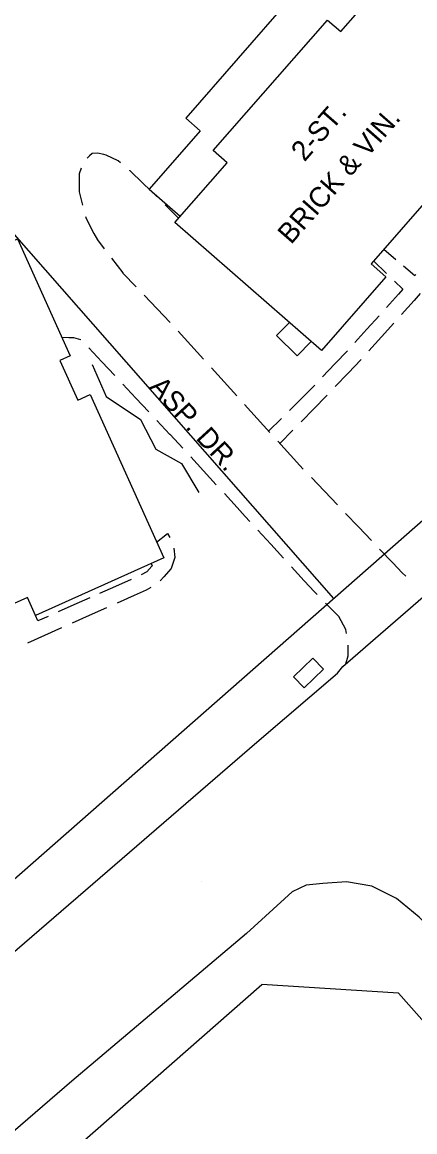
# Model space of a CAD drawing. Extents: x 2443269 to 2494951, y 591171 to 622130.
# Drawn here: x 2462410.9 to 2462491.9, y 604001.8 to 604230.6 of the extents above; entities that cross this region are included whole.
import ezdxf

# ---------------------------------------------------------------- set-up
doc = ezdxf.new("R2010")
doc.units = 0
for name, color, linetype in [('SURVEY - NON-TRANSPORTATION - Buildings', 7, 'Continuous'), ('SURVEY - NON-TRANSPORTATION - Buildings Text', 7, 'Continuous'), ('SURVEY - NON-TRANSPORTATION - Features', 7, 'Continuous'), ('SURVEY - PROPERTY - Property Lines', 7, 'Continuous'), ('SURVEY - PROPERTY - ROW Lines', 7, 'Continuous'), ('SURVEY - TRANSPORTATION - Features', 7, 'Continuous'), ('SURVEY - TRANSPORTATION - Features Text', 7, 'Continuous'), ('SURVEY - TRANSPORTATION - Roads', 7, 'Continuous')]:
    doc.layers.add(name, color=color, linetype=linetype)

msp = doc.modelspace()

# ---------------------------------------------------------------- linework, layer by layer
at = {"layer": 'SURVEY - NON-TRANSPORTATION - Buildings'}
for points in [[(2462442.414, 604189.35), (2462453.178, 604201.646), (2462450.334, 604204.137), (2462473.89, 604231.053), (2462476.61, 604228.671), (2462487.141, 604240.701), (2462517.338, 604214.271), (2462503.897, 604198.913), (2462500.954, 604201.489), (2462482.844, 604180.797), (2462485.914, 604178.11), (2462472.617, 604162.916)], [(2462330.229, 604111.45), (2462353.392, 604121.886), (2462351.827, 604125.36), (2462353.142, 604125.951), (2462351.062, 604130.567), (2462327.024, 604119.737), (2462316.345, 604143.444), (2462338.638, 604153.487), (2462336.935, 604157.27), (2462386.213, 604179.468), (2462387.788, 604175.974), (2462409.983, 604185.974), (2462420.855, 604161.84), (2462418.713, 604160.876), (2462422.397, 604152.7), (2462424.953, 604153.851), (2462440.111, 604120.206), (2462413.68, 604108.3), (2462412.004, 604112.024), (2462370.199, 604093.192), (2462371.879, 604089.465), (2462345.488, 604077.575)]]:
    msp.add_lwpolyline(points, close=True, dxfattribs=at)
at = {"layer": 'SURVEY - NON-TRANSPORTATION - Features'}
for points in [[(2462486.315, 604239.757), (2462480.052, 604245.219), (2462469.349, 604232.946), (2462466.262, 604235.639), (2462444.648, 604210.856), (2462447.647, 604208.241), (2462437.122, 604196.174), (2462443.51, 604190.603)], [(2462470.504, 604164.767), (2462467.597, 604161.82), (2462463.349, 604166.01), (2462466.006, 604168.704)], [(2462425.383, 604160.055), (2462428.231, 604153.458), (2462435.298, 604148.727), (2462438.516, 604142.578), (2462443.775, 604139.603), (2462447.361, 604133.631)]]:
    msp.add_lwpolyline(points, dxfattribs=at)
msp.add_lwpolyline([(2462469.048, 604093.385), (2462466.872, 604095.636), (2462470.849, 604099.478), (2462473.024, 604097.227)], close=True, dxfattribs=at)
at = {"layer": 'SURVEY - PROPERTY - Property Lines'}
for p, q in [((2462475.153, 604111.816), (2462362.973, 604239.515)), ((2462488.535, 604030.399), (2462460.314, 604032.225))]:
    msp.add_line(p, q, dxfattribs=at)
at = {"layer": 'SURVEY - PROPERTY - ROW Lines'}
for p, q in [((2462271.547, 603932.954), (2462848.45, 604439.747)), ((2462295.189, 603887.17), (2462460.311, 604032.225)), ((2462574.391, 603932.665), (2462488.535, 604030.399))]:
    msp.add_line(p, q, dxfattribs=at)
at = {"layer": 'SURVEY - TRANSPORTATION - Features'}
for p, q in [((2462424.799, 604203.08), (2462424.329, 604202.555)), ((2462425.35, 604203.533), (2462424.799, 604203.08)), ((2462426.446, 604203.612), (2462425.35, 604203.533)), ((2462427.784, 604203.328), (2462426.446, 604203.612)), ((2462428.27, 604203.224), (2462427.784, 604203.328)), ((2462430.721, 604202.014), (2462428.27, 604203.224)), ((2462431.233, 604201.607), (2462430.721, 604202.014)), ((2462423.089, 604200.516), (2462422.66, 604199.363)), ((2462422.66, 604199.363), (2462422.695, 604196.709)), ((2462433.162, 604200.072), (2462433.133, 604200.095)), ((2462435.909, 604197.377), (2462433.162, 604200.072)), ((2462438.682, 604194.657), (2462435.909, 604197.377)), ((2462422.695, 604196.709), (2462422.709, 604195.623)), ((2462422.709, 604195.623), (2462423.401, 604192.911)), ((2462443.188, 604190.236), (2462440.415, 604192.956)), ((2462424.002, 604190.559), (2462424.11, 604190.134)), ((2462424.11, 604190.134), (2462425.718, 604187.086)), ((2462425.718, 604187.086), (2462426.433, 604185.731)), ((2462426.433, 604185.731), (2462427.865, 604183.863)), ((2462487.974, 604181.646), (2462485.458, 604183.786)), ((2462485.458, 604183.786), (2462485.458, 604183.786)), ((2462429.342, 604181.937), (2462431.653, 604178.923)), ((2462483.378, 604181.407), (2462486.045, 604178.83)), ((2462431.653, 604178.923), (2462431.713, 604178.86)), ((2462431.713, 604178.86), (2462434.406, 604176.06)), ((2462491.846, 604178.353), (2462489.546, 604180.309)), ((2462487.712, 604177.22), (2462489.412, 604175.577)), ((2462492.03, 604178.566), (2462491.846, 604178.353)), ((2462436.089, 604174.31), (2462438.782, 604171.51)), ((2462488.514, 604174.577), (2462486.036, 604171.818)), ((2462489.412, 604175.577), (2462488.514, 604174.577)), ((2462492.994, 604174.658), (2462491.721, 604173.24)), ((2462491.721, 604173.24), (2462489.149, 604170.375)), ((2462438.782, 604171.51), (2462441.475, 604168.71)), ((2462484.488, 604170.094), (2462482.01, 604167.335)), ((2462482.01, 604167.335), (2462479.532, 604164.576)), ((2462487.541, 604168.585), (2462484.968, 604165.72)), ((2462420.554, 604165.534), (2462419.169, 604165.583)), ((2462421.558, 604165.521), (2462420.554, 604165.534)), ((2462423.014, 604165.141), (2462421.558, 604165.521)), ((2462423.021, 604165.136), (2462423.014, 604165.141)), ((2462443.115, 604166.92), (2462445.721, 604164.039)), ((2462484.968, 604165.72), (2462482.396, 604162.855)), ((2462427.379, 604160.604), (2462424.712, 604163.454)), ((2462445.721, 604164.039), (2462448.327, 604161.157)), ((2462477.965, 604162.869), (2462475.41, 604160.182)), ((2462430.045, 604157.754), (2462427.379, 604160.604)), ((2462480.782, 604161.07), (2462478.128, 604158.28)), ((2462449.955, 604159.357), (2462452.561, 604156.475)), ((2462475.41, 604160.182), (2462472.854, 604157.495)), ((2462478.128, 604158.28), (2462475.475, 604155.49)), ((2462434.378, 604153.122), (2462431.712, 604155.972)), ((2462452.561, 604156.475), (2462455.167, 604153.594)), ((2462471.246, 604155.803), (2462468.631, 604153.197)), ((2462471.257, 604155.815), (2462471.246, 604155.803)), ((2462473.598, 604153.517), (2462471.121, 604150.996)), ((2462473.816, 604153.746), (2462473.598, 604153.517)), ((2462437.045, 604150.272), (2462434.378, 604153.122)), ((2462456.795, 604151.793), (2462459.401, 604148.912)), ((2462468.631, 604153.197), (2462466.005, 604150.579)), ((2462459.401, 604148.912), (2462462.007, 604146.03)), ((2462464.364, 604148.943), (2462461.738, 604146.325)), ((2462471.121, 604150.996), (2462468.423, 604148.249)), ((2462441.378, 604145.641), (2462438.712, 604148.491)), ((2462441.416, 604145.6), (2462441.378, 604145.641)), ((2462444.021, 604142.769), (2462441.416, 604145.6)), ((2462466.736, 604146.532), (2462464.038, 604143.786)), ((2462463.635, 604144.229), (2462466.241, 604141.348)), ((2462448.315, 604138.101), (2462445.672, 604140.973)), ((2462466.241, 604141.348), (2462468.181, 604139.202)), ((2462450.957, 604135.228), (2462448.315, 604138.101)), ((2462468.181, 604139.202), (2462468.866, 604138.485)), ((2462470.542, 604136.728), (2462473.224, 604133.918)), ((2462455.251, 604130.56), (2462452.609, 604133.433)), ((2462473.224, 604133.918), (2462475.906, 604131.107)), ((2462456.932, 604128.733), (2462455.251, 604130.56)), ((2462457.891, 604127.685), (2462456.932, 604128.733)), ((2462477.582, 604129.35), (2462480.264, 604126.54)), ((2462480.264, 604126.54), (2462482.946, 604123.729)), ((2462438.654, 604123.438), (2462440.885, 604125.216)), ((2462440.885, 604125.216), (2462441.392, 604124.362)), ((2462462.172, 604123.006), (2462459.537, 604125.886)), ((2462442.219, 604122.166), (2462442.381, 604120.275)), ((2462464.807, 604120.127), (2462462.172, 604123.006)), ((2462484.622, 604121.972), (2462487.304, 604119.162)), ((2462442.381, 604120.275), (2462441.767, 604118.426)), ((2462436.626, 604117.293), (2462435.439, 604116.665)), ((2462437.689, 604118.461), (2462436.626, 604117.293)), ((2462437.506, 604119.032), (2462437.742, 604118.523)), ((2462437.742, 604118.523), (2462437.689, 604118.461)), ((2462441.626, 604118.002), (2462440.147, 604116.286)), ((2462441.767, 604118.426), (2462441.626, 604118.002)), ((2462469.089, 604115.448), (2462466.454, 604118.327)), ((2462487.304, 604119.162), (2462489.294, 604117.076)), ((2462489.294, 604117.076), (2462490.018, 604116.383)), ((2462433.418, 604115.731), (2462430.161, 604114.28)), ((2462440.147, 604116.286), (2462439.384, 604115.447)), ((2462471.18, 604113.162), (2462469.089, 604115.448)), ((2462430.161, 604114.28), (2462426.905, 604112.83)), ((2462434.004, 604112.401), (2462430.49, 604110.836)), ((2462436.466, 604113.497), (2462434.004, 604112.401)), ((2462437.484, 604114.034), (2462436.466, 604113.497)), ((2462471.749, 604112.592), (2462471.18, 604113.162)), ((2462421.614, 604110.473), (2462418.358, 604109.023)), ((2462424.87, 604111.923), (2462421.614, 604110.473)), ((2462476.144, 604108.182), (2462473.471, 604110.864)), ((2462414.202, 604107.172), (2462413.68, 604108.3)), ((2462413.68, 604108.3), (2462413.68, 604108.3)), ((2462416.322, 604108.116), (2462414.202, 604107.172)), ((2462424.781, 604108.293), (2462421.267, 604106.728)), ((2462428.294, 604109.858), (2462424.781, 604108.293)), ((2462476.2, 604108.08), (2462476.144, 604108.182)), ((2462477.666, 604105.426), (2462476.2, 604108.08)), ((2462419.071, 604105.75), (2462415.558, 604104.185)), ((2462415.558, 604104.185), (2462412.044, 604102.62)), ((2462477.821, 604104.569), (2462477.666, 604105.426)), ((2462478.155, 604099.947), (2462478.113, 604102.155)), ((2462477.67, 604098.323), (2462478.155, 604099.947))]:
    msp.add_line(p, q, dxfattribs=at)
at = {"layer": 'SURVEY - TRANSPORTATION - Roads'}
msp.add_line((2462447.859, 604053.49), (2462447.859, 604053.49), dxfattribs=at)
for points in [[(2462389.212, 604021.726), (2462428.549, 604055.61), (2462459.32, 604082.195), (2462475.901, 604096.433), (2462477.017, 604097.756), (2462495.629, 604113.92)], [(2462577.873, 603948.812), (2462556.242, 603973.497), (2462538.313, 603994.311), (2462521.643, 604013.563), (2462506.685, 604031.151), (2462498.477, 604040.18), (2462492.791, 604046.082), (2462488.09, 604049.964), (2462483.004, 604052.483), (2462477.814, 604053.359), (2462472.883, 604053.048), (2462469.5, 604052.72), (2462466.564, 604051.289), (2462457.161, 604042.723), (2462421.147, 604012.27)], [(2462421.147, 604012.27), (2462393.434, 603988.376), (2462358.818, 603958.232), (2462330.56, 603933.78), (2462305.951, 603912.733), (2462286.066, 603895.45), (2462282.798, 603892.687), (2462276.994, 603887.625), (2462274.491, 603885.233), (2462272.043, 603881.26), (2462270.928, 603879.767), (2462268.848, 603872.497), (2462268.815, 603867.274), (2462270.616, 603859.961), (2462276.978, 603842.231), (2462283.195, 603824.026), (2462288.346, 603804.623), (2462290.488, 603793.124), (2462292.562, 603772.658), (2462293.277, 603753.921), (2462293.034, 603742.91)]]:
    msp.add_lwpolyline(points, dxfattribs=at)

# ---------------------------------------------------------------- texts
at = {"layer": 'SURVEY - NON-TRANSPORTATION - Buildings Text'}
for s, p in [('2-ST.', (2462469.119, 604201.689)), ('BRICK & VIN. ', (2462466.355, 604184.641))]:
    msp.add_text(s, height=4.166, rotation=48.80806, dxfattribs=at).set_placement(p)
at = {"layer": 'SURVEY - TRANSPORTATION - Features Text'}
msp.add_text('ASP. DR.', height=4.166, rotation=312.60971, dxfattribs=at).set_placement((2462436.921, 604155.25))

doc.saveas('drawing.dxf')
